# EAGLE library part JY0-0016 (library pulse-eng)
RJ45/Dual USB Combo
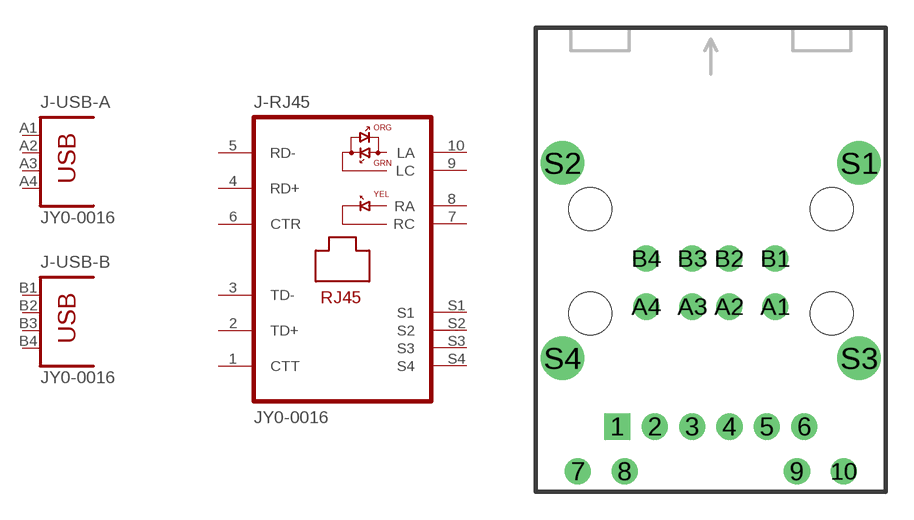
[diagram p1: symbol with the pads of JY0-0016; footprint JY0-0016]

Designator prefix J; gates -RJ45=JY0-0016 -USB-A=USB-4 -USB-B=USB-4

## JY0-0016  [JY0-0016]
1  -RJ45:CTT
2  -RJ45:TD+
3  -RJ45:TD-
4  -RJ45:RD+
5  -RJ45:RD-
6  -RJ45:CTR
7  -RJ45:RC  pas
8  -RJ45:RA  pas
9  -RJ45:LC  pas
10  -RJ45:LA  pas
A1  -USB-A:1  pas
A2  -USB-A:2  pas
A3  -USB-A:3  pas
A4  -USB-A:4  pas
B1  -USB-B:1  pas
B2  -USB-B:2  pas
B3  -USB-B:3  pas
B4  -USB-B:4  pas
S1  -RJ45:S1  pas
S2  -RJ45:S2  pas
S3  -RJ45:S3  pas
S4  -RJ45:S4  pas

## Footprint JY0-0016 (pad centres in mm)
RJ45/Dual USB Combo
drill 0.914 square: 1 -5.08,-14.351
drill 0.914 round: 2 -3.048,-14.351; 3 -1.016,-14.351; 4 1.016,-14.351; 5 3.048,-14.351; 6 5.08,-14.351; 7 -7.226,-16.789; 8 -4.686,-16.789; 9 4.686,-16.789; 10 7.226,-16.789; A1 3.505,-7.823; A2 1.003,-7.823; A3 -1.003,-7.823; A4 -3.505,-7.823; B1 3.505,-5.207; B2 1.003,-5.207; B3 -1.003,-5.207; B4 -3.505,-5.207
drill 1.575 round: S1 8.065,0; S2 -8.065,0; S3 8.065,-10.617; S4 -8.065,-10.617
hole 2.337 at -6.566,-2.515
hole 2.337 at 6.566,-2.515
hole 2.337 at 6.566,-8.204
hole 2.337 at -6.566,-8.204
